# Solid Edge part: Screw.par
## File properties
Title: Screw
Author: Deepak Maini
Template: Normal.par
Last saved by: CADCIM
Revision: 8
Application: Solid Edge
Material: aluminum
Accuracy: 0.99
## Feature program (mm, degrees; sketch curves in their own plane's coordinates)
sketch for "unnamed Protrusion 1" plane through (0, 0, 0) normal (0, -1, 0) x-axis (1, 0, 0)
  circle centre (0, 0) radius 12.5
extrude "unnamed Protrusion 1" add finite 25 along +normal
sketch for "ExtrudedProtrusion_2" plane through (0, -25, 0) normal (0, -1, 0) x-axis (1, 0, 0)
  circle centre (0, 0) radius 10
extrude "ExtrudedProtrusion_2" add finite 96 along +normal
sketch for "ExtrudedProtrusion_3" plane through (0, -121, 0) normal (0, -1, 0) x-axis (1, 0, 0)
  circle centre (0, 0) radius 6
extrude "ExtrudedProtrusion_3" add finite 4 along +normal
sketch for "ExtrudedProtrusion_4" plane through (0, -125, 0) normal (0, -1, 0) x-axis (1, 0, 0)
  circle centre (0, 0) radius 4
extrude "ExtrudedProtrusion_4" add finite 6 along +normal
sketch for "unnamed RevolvedProtrusion 1" plane through (0, 0, 0) normal (0, 0, 1) x-axis (1, 0, 0)
  line (0, -131) -> (6, -131)
  line (6, -131) -> (6, -141)
  line (6, -141) -> (0, -143.8522)
  line (0, -143.8522) -> (0, -131)
revolve "unnamed RevolvedProtrusion 1" add full turn 360 deg about sketch line (0, -131) -> (0, -106.3065)
sketch for "ExtrudedCutout_1" plane through (0, 0, 0) normal (1, 0, 0) x-axis (0, 1, 0)
  circle centre (-13, 0) radius 5.5
extrude "ExtrudedCutout_1" cut finite 222.1 symmetric
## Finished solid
Body 1: solid body, 12 faces, 12 edges, 1 vertex.
  Faces by surface: cylinder 6, plane 5, cone 1
  Edges by curve: circle 10, intersection 2
Bounding box of the edges (mm): 25.000 x 141.000 x 25.000, from (-12.5, -141, -12.5) to (12.5, 0, 12.5).
Cylindrical faces by radius (mm): R4 x1, R5.5 x1, R6 x2, R10 x1, R12.5 x1
Conical faces (half-angle, radius in mm at the cone's reference point): 64.5754 deg R6 x1
Planar faces by outward normal: +y 2, -y 3
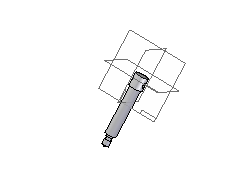
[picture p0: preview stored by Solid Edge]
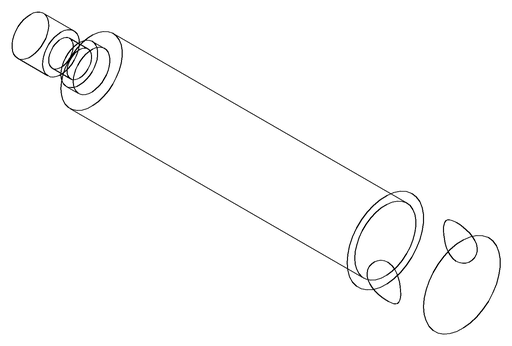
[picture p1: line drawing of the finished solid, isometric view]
